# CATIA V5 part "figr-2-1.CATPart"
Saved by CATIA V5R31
Part number: figr-2-1
Bounding box of the stored display mesh (mm): x 0 to 10, y -99.811 to 99.811, z -49.833 to 49.833
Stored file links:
  D:\PROJECTS\Project 2021\US EDITION\CATIA V5 6R 2021\Resources\Part Files\c02_catia_v5_6r2021_prt\figr-2-1.CATPart
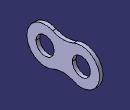
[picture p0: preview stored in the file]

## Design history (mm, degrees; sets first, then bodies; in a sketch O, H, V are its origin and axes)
Body1 (main body)
  Sketch1 on yz-plane, origin (0, 0, 0), H (0, 1, 0), V (0, 0, 1)
    arc A1 centre (50, 0) radius 50 from (29.1667, -45.453) to (29.1666, 45.4529) ccw
    point P1 (50, 0)
    arc A2 centre (-50, 0) radius 50 from (-29.1666, 45.4529) to (-29.1667, -45.453) ccw
    point P2 (-50, 0)
    arc A3 centre (0, 109.0871) radius 70 from (-29.1666, 45.4529) to (29.1667, 45.453) ccw
    point P4 (-29.1666, 45.4529)
    point P5 (0, 39.0871)
    point P6 (29.1667, 45.453)
    point P7 (29.1667, -45.453)
    point P8 (-29.1666, -45.4529)
    arc A4 centre (0, -109.0871) radius 70 from (-29.1666, -45.4529) to (29.1667, -45.453) cw
    point P10 (-29.1667, -45.453)
    point P11 (-29.1666, 45.4529)
    point P12 (29.1666, 45.4529)
    point P13 (29.1667, -45.453)
    circle A5 centre (50, 0) radius 25
    circle A6 centre (-50, 0) radius 25
    distance P1 P2 = 100
    radius A1 = 50
    radius A2 = 50
    distance O P2 = 50
    radius A5 = 25
    radius A6 = 25
    radius A3 = 70
    coincidence: P1 H, P2 H, P4 A2, A3 P5, P5 V, P6 A1, A4 P10, A3 P11, A3 P12, A4 P13
    tangency: A3 A1, A3 A2
    symmetry: P6 P7 H, P4 P8 H, A3 A4 H
  Pad1: profile Sketch1, direction (1, 0, 0), length 10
